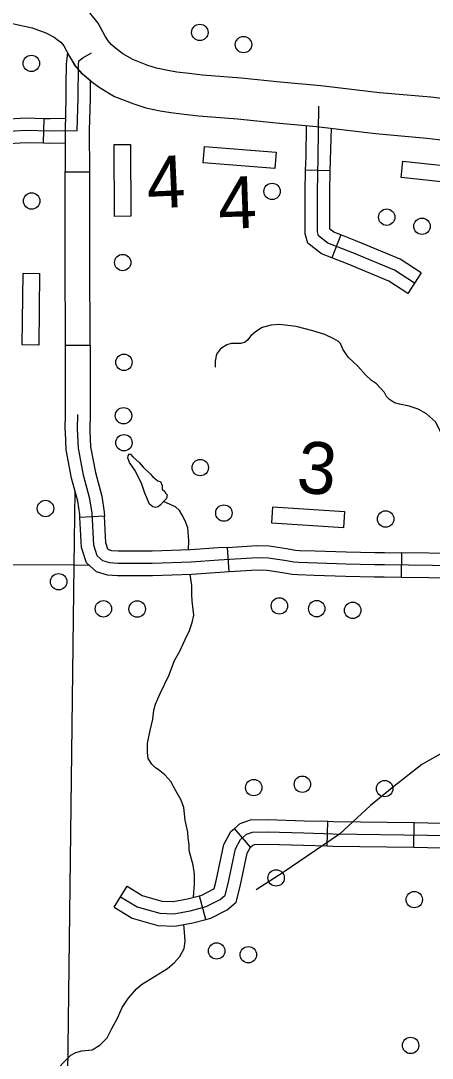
# Model space of a CAD drawing. Extents: x 22866 to 28196, y 1324810 to 1328105.
# Drawn here: x 25465.4 to 25525.6, y 1326340.7 to 1326492.6 of the extents above; entities that cross this region are included whole.
import ezdxf

# ---------------------------------------------------------------- set-up
doc = ezdxf.new("R2010")
doc.units = 0
for name, color, linetype in [('Level 10', 7, 'Continuous'), ('Level 31', 7, 'Continuous'), ('Level 32', 7, 'Continuous'), ('Level 34', 7, 'Continuous'), ('Level 35', 7, 'Continuous'), ('Level 5', 7, 'Continuous'), ('Level 56', 7, 'Continuous')]:
    doc.layers.add(name, color=color, linetype=linetype)

msp = doc.modelspace()

# ---------------------------------------------------------------- linework, layer by layer
at = {"layer": 'Level 10'}
for points in [[(25483.97, 1326486.04), (25481.75, 1326486.89), (25480.32, 1326487.75), (25479.48, 1326488.37), (25478.6, 1326489.1), (25478.14, 1326489.62), (25477.72, 1326490.32), (25476.7, 1326492.23), (25475.5, 1326493.72), (25474.58, 1326494.45), (25473.43, 1326495.3), (25471.42, 1326496.33), (25468.7, 1326497.28), (25466.13, 1326497.87), (25462.9, 1326498.6), (25457.93, 1326499.47), (25456.22, 1326499.8), (25452.62, 1326500.3), (25449.84, 1326500.5), (25447.36, 1326500.74), (25445.63, 1326500.86), (25443.19, 1326500.9), (25441.23, 1326500.79)], [(25442.62, 1326494.91), (25445.36, 1326494.86), (25446.86, 1326494.76), (25449.34, 1326494.52), (25452, 1326494.33), (25455.25, 1326493.88), (25456.85, 1326493.57), (25461.72, 1326492.71), (25464.8, 1326492.02), (25467.03, 1326491.51), (25469.04, 1326490.8), (25470.26, 1326490.18), (25470.92, 1326489.69), (25471.25, 1326489.43), (25471.68, 1326488.9), (25472.5, 1326487.35), (25473.27, 1326486.08), (25474.39, 1326484.79), (25475.79, 1326483.63), (25477, 1326482.75), (25479.11, 1326481.48), (25481.94, 1326480.39)], [(25559.75, 1326467.42), (25556.83, 1326471.16), (25554.9, 1326473.34), (25552.99, 1326475.26), (25551.5, 1326476.55), (25549.59, 1326477.63), (25547.36, 1326478.5), (25543.35, 1326479.14), (25539.62, 1326479.66), (25533.77, 1326480.34), (25525.38, 1326481.37), (25517.87, 1326482.04), (25509.28, 1326483.06), (25503.31, 1326483.58), (25497.62, 1326484.17), (25491.97, 1326484.6), (25489.99, 1326484.83), (25488.21, 1326485.06), (25486.87, 1326485.28), (25485.22, 1326485.62), (25483.97, 1326486.04)], [(25481.94, 1326480.39), (25483.65, 1326479.82), (25485.78, 1326479.37), (25487.35, 1326479.12), (25489.27, 1326478.87), (25491.39, 1326478.63), (25497.08, 1326478.19), (25502.74, 1326477.6), (25508.66, 1326477.09), (25517.25, 1326476.07), (25524.75, 1326475.4), (25533.06, 1326474.38), (25538.86, 1326473.71), (25542.46, 1326473.21), (25545.78, 1326472.67), (25547.01, 1326472.2), (25548.02, 1326471.62), (25548.89, 1326470.86), (25550.53, 1326469.23), (25552.22, 1326467.32), (25554.95, 1326463.82)]]:
    msp.add_lwpolyline(points, dxfattribs=at)
at = {"layer": 'Level 31'}
for p, q in [((25471.86, 1326470.43), (25475.46, 1326470.43)), ((25471.91, 1326445.08), (25475.51, 1326445.08)), ((25477.63, 1326420.05), (25474.03, 1326419.86)), ((25474.03, 1326419.86), (25474.03, 1326419.86)), ((25495.85, 1326411.87), (25495.64, 1326415.47)), ((25521.05, 1326414.67), (25521.01, 1326411.07))]:
    msp.add_line(p, q, dxfattribs=at)
for points in [[(25472.21, 1326487.9), (25472.01, 1326486.19), (25471.99, 1326483.12)], [(25475.59, 1326483.79), (25474.38, 1326484.8), (25473.26, 1326486.1), (25472.21, 1326487.9)], [(25475.59, 1326483.09), (25475.59, 1326483.79)], [(25471.99, 1326483.12), (25471.97, 1326481.32), (25471.85, 1326476.54), (25471.86, 1326470.43)], [(25475.46, 1326470.43), (25475.45, 1326476.5), (25475.57, 1326481.26), (25475.59, 1326483.08)], [(25441.82, 1326456.87), (25443.46, 1326458.92), (25446.53, 1326461.72), (25450.22, 1326464.53), (25451.96, 1326466.89), (25455.31, 1326471.03), (25456.44, 1326472.43), (25457.02, 1326473.66), (25457.36, 1326475.16), (25457.36, 1326476.11), (25457.63, 1326476.69), (25458.65, 1326477.34), (25459.14, 1326477.37), (25459.72, 1326477.17), (25460.68, 1326476.89), (25461.6, 1326476.52), (25462.9, 1326476.35), (25466.11, 1326476.55), (25469.66, 1326476.45), (25473.65, 1326476.52)], [(25471.88, 1326457.75), (25471.86, 1326470.43)], [(25475.48, 1326457.76), (25475.46, 1326470.43)], [(25471.91, 1326445.08), (25471.88, 1326457.75)], [(25475.51, 1326445.08), (25475.48, 1326457.76)], [(25471.9, 1326432.34), (25471.89, 1326432.76), (25471.92, 1326434.95), (25471.91, 1326445.08)], [(25475.51, 1326445.08), (25475.52, 1326434.93), (25475.49, 1326432.8), (25475.5, 1326432.48)], [(25474.03, 1326419.86), (25474.01, 1326420.27), (25473.71, 1326422.22), (25472.81, 1326425.62), (25472, 1326429.76), (25471.9, 1326432.34)], [(25475.5, 1326432.48), (25475.59, 1326430.18), (25476.32, 1326426.43), (25477.24, 1326422.96), (25477.6, 1326420.64), (25477.63, 1326420.05)], [(25483.09, 1326411.32), (25482.72, 1326411.32), (25479.51, 1326411.32), (25478.09, 1326411.4), (25476.47, 1326411.87), (25475.01, 1326413.2), (25474.27, 1326415.45), (25474.03, 1326419.86)], [(25483.09, 1326414.92), (25482.72, 1326414.92), (25479.62, 1326414.92), (25478.7, 1326414.97), (25478.27, 1326415.1), (25478.13, 1326415.22), (25477.84, 1326416.12), (25477.63, 1326420.05)], [(25495.64, 1326415.47), (25494.25, 1326415.39), (25490.22, 1326415.1), (25484.59, 1326414.92), (25483.09, 1326414.92)], [(25495.64, 1326415.47), (25499.92, 1326415.72), (25501.71, 1326415.68), (25504.24, 1326415.3), (25505.55, 1326415.08), (25506.14, 1326415.02), (25508.42, 1326414.95)], [(25508.42, 1326414.95), (25512.99, 1326414.81), (25517.16, 1326414.7), (25518.57, 1326414.7), (25521.05, 1326414.67)], [(25533.65, 1326414.73), (25529.09, 1326414.58), (25521.05, 1326414.67)], [(25508.31, 1326411.35), (25505.9, 1326411.43), (25505.08, 1326411.51), (25503.68, 1326411.74), (25501.4, 1326412.09), (25499.98, 1326412.12), (25495.85, 1326411.87)], [(25495.85, 1326411.87), (25494.48, 1326411.79), (25490.41, 1326411.5), (25484.65, 1326411.32), (25483.09, 1326411.32)], [(25521.01, 1326411.07), (25518.55, 1326411.1), (25517.12, 1326411.1), (25512.89, 1326411.21), (25508.31, 1326411.35)], [(25533.76, 1326411.13), (25529.13, 1326410.98), (25521.01, 1326411.07)]]:
    msp.add_lwpolyline(points, dxfattribs=at)
at = {"layer": 'Level 32'}
for p, q in [((25468.7, 1326474.68), (25468.8, 1326478.28)), ((25510.65, 1326470.6), (25507.05, 1326470.7)), ((25512.21, 1326461.21), (25510.9, 1326457.86)), ((25523.96, 1326455.66), (25522, 1326452.64)), ((25498.99, 1326371.59), (25496.63, 1326374.31)), ((25510.19, 1326371.76), (25510.29, 1326375.36)), ((25522.89, 1326371.57), (25522.94, 1326375.17)), ((25479.05, 1326362.79), (25480.93, 1326365.86)), ((25492.47, 1326361), (25491.54, 1326364.47))]:
    msp.add_line(p, q, dxfattribs=at)
for points in [[(25473.65, 1326476.52), (25473.77, 1326481.29), (25473.81, 1326486.07), (25473.88, 1326486.7), (25474.47, 1326487.13), (25475.71, 1326487.85)], [(25455.56, 1326475.55), (25455.56, 1326476.51), (25456.23, 1326477.93), (25458.07, 1326479.1), (25459.39, 1326479.19), (25460.27, 1326478.88), (25461.26, 1326478.6), (25462.06, 1326478.27), (25462.96, 1326478.15), (25466.08, 1326478.35), (25468.8, 1326478.28)], [(25520.05, 1326456.05), (25513.95, 1326458.59), (25510.28, 1326460.03), (25508.94, 1326461.06), (25508.77, 1326461.65), (25508.77, 1326462.49), (25508.77, 1326467.53), (25508.9, 1326472.61), (25508.97, 1326480.08)], [(25468.8, 1326478.28), (25469.67, 1326478.25), (25471.9, 1326478.29)], [(25507.05, 1326470.7), (25507.1, 1326472.64), (25507.15, 1326477.22)], [(25510.65, 1326470.6), (25510.82, 1326476.84)], [(25459.16, 1326475.45), (25459.17, 1326475.45), (25460.09, 1326475.19), (25461.13, 1326474.76), (25462.84, 1326474.54), (25466.14, 1326474.75), (25468.7, 1326474.68)], [(25468.7, 1326474.68), (25469.65, 1326474.65), (25471.85, 1326474.69)], [(25510.9, 1326457.86), (25509.38, 1326458.45), (25507.38, 1326459.99), (25506.97, 1326461.39), (25506.97, 1326462.49), (25506.97, 1326467.56), (25507.05, 1326470.7)], [(25512.21, 1326461.21), (25511.17, 1326461.62), (25510.57, 1326462.08), (25510.57, 1326462.49), (25510.57, 1326467.51), (25510.65, 1326470.6)], [(25523.96, 1326455.66), (25520.89, 1326457.65), (25514.62, 1326460.26), (25512.21, 1326461.21)], [(25522, 1326452.64), (25519.21, 1326454.45), (25513.27, 1326456.92), (25510.9, 1326457.86)], [(25522.98, 1326454.15), (25520.05, 1326456.05)], [(25479.56, 1326413.12), (25478.39, 1326413.19), (25477.37, 1326413.48), (25476.57, 1326414.21), (25476.06, 1326415.78), (25475.8, 1326420.46), (25475.48, 1326422.59), (25474.56, 1326426.03), (25473.8, 1326429.97), (25473.69, 1326432.78), (25473.72, 1326434.94)], [(25529.11, 1326412.78), (25518.56, 1326412.9), (25517.14, 1326412.9), (25512.94, 1326413.01), (25506.02, 1326413.23), (25505.31, 1326413.3), (25503.96, 1326413.52), (25501.55, 1326413.88), (25499.95, 1326413.92), (25494.37, 1326413.59), (25490.31, 1326413.3), (25484.62, 1326413.12), (25482.72, 1326413.12), (25479.56, 1326413.12)], [(25491.54, 1326364.47), (25491.88, 1326364.56), (25493.54, 1326365.4), (25493.67, 1326365.51), (25493.98, 1326366.66), (25495.08, 1326371.97), (25496.1, 1326373.86), (25496.63, 1326374.31)], [(25496.63, 1326374.31), (25497.47, 1326375.04), (25498.97, 1326375.57), (25501.5, 1326375.61), (25506.82, 1326375.45), (25510.29, 1326375.36)], [(25510.29, 1326375.36), (25511.11, 1326375.34), (25522.94, 1326375.17)], [(25522.94, 1326375.17), (25524.91, 1326375.14), (25533.99, 1326375.02), (25535.82, 1326374.76)], [(25495.73, 1326366.24), (25496.79, 1326371.34), (25497.53, 1326372.71), (25498.39, 1326373.46), (25499.29, 1326373.77), (25501.49, 1326373.81), (25506.77, 1326373.65), (25511.07, 1326373.54), (25524.88, 1326373.34), (25533.85, 1326373.22), (25536.05, 1326372.91), (25536.59, 1326372.52), (25536.95, 1326372.08), (25536.99, 1326371.38), (25536.91, 1326369.22), (25536.85, 1326363.05)], [(25492.47, 1326361), (25493.17, 1326361.18), (25495.58, 1326362.39), (25496.87, 1326363.53), (25497.48, 1326365.83), (25498.49, 1326370.71), (25498.96, 1326371.57), (25498.99, 1326371.59)], [(25498.99, 1326371.59), (25499.31, 1326371.87), (25499.61, 1326371.98), (25501.48, 1326372.01), (25506.72, 1326371.85), (25510.19, 1326371.76)], [(25510.19, 1326371.76), (25511.03, 1326371.74), (25522.89, 1326371.57)], [(25522.89, 1326371.57), (25524.86, 1326371.54), (25533.71, 1326371.42), (25535.31, 1326371.19)], [(25479.99, 1326364.32), (25482.42, 1326362.83), (25485.71, 1326361.89), (25487.79, 1326361.81), (25490.17, 1326362.25), (25492.52, 1326362.87), (25494.56, 1326363.89), (25495.27, 1326364.52), (25495.73, 1326366.24)], [(25480.93, 1326365.86), (25483.15, 1326364.5), (25486, 1326363.68), (25487.66, 1326363.62), (25489.78, 1326364), (25491.54, 1326364.47)], [(25479.05, 1326362.79), (25481.69, 1326361.17), (25485.42, 1326360.1), (25487.91, 1326360.01), (25490.57, 1326360.49), (25492.47, 1326361)]]:
    msp.add_lwpolyline(points, dxfattribs=at)
at = {"layer": 'Level 34'}
msp.add_lwpolyline([(25533.04, 1326388.54), (25528.54, 1326386.21), (25524.03, 1326383.66), (25519.71, 1326380.28), (25516.54, 1326377.69), (25511.99, 1326373.49), (25503.77, 1326367.86), (25499.81, 1326365.31)], dxfattribs=at)
at = {"layer": 'Level 35'}
for points in [[(25512.47, 1326444.48), (25512.17, 1326445.31), (25511.85, 1326445.63), (25511.17, 1326446.02), (25509.84, 1326446.62), (25508.09, 1326447.17), (25505.66, 1326447.8), (25503.2, 1326448.11), (25502, 1326448.01), (25500.69, 1326447.64), (25499.73, 1326447.04), (25498.99, 1326446.41), (25498.58, 1326445.84), (25498.18, 1326445.52), (25497.56, 1326445.31), (25496.9, 1326445.31), (25496.14, 1326445.31), (25495.52, 1326445.13), (25494.6, 1326444.55), (25494, 1326443.74), (25493.79, 1326442.75), (25493.79, 1326441.86)], [(25523.52, 1326435.68), (25522.2, 1326436.13), (25520.79, 1326436.42), (25520.05, 1326436.63), (25519.3, 1326437.1), (25518.88, 1326437.57), (25518.59, 1326438.12), (25517.41, 1326439.4), (25516.68, 1326439.92), (25515.82, 1326440.71), (25514.69, 1326441.99), (25513.31, 1326443.25), (25512.76, 1326444.06), (25512.47, 1326444.48)], [(25538.62, 1326421.96), (25537.06, 1326422.65), (25534.89, 1326423.88), (25533.74, 1326425.03), (25532.96, 1326425.5), (25532.41, 1326425.6), (25531.81, 1326425.84), (25531.26, 1326426.39), (25530.74, 1326426.97), (25530.29, 1326427.46), (25529.85, 1326427.91), (25529.14, 1326428.51), (25528.31, 1326429.37), (25527.47, 1326430.44), (25527.13, 1326431.33), (25526.87, 1326432.2), (25526.55, 1326432.9), (25526.03, 1326433.87), (25524.72, 1326435), (25523.52, 1326435.68)], [(25482.99, 1326424.96), (25482.05, 1326426.76), (25481.3, 1326427.87), (25481.05, 1326428.58), (25481.08, 1326428.87), (25481.26, 1326429.15), (25481.44, 1326429.12), (25481.76, 1326428.72), (25482.72, 1326427.87), (25483.26, 1326427.19), (25484.36, 1326426.16), (25484.68, 1326425.77)], [(25484.68, 1326425.77), (25485.43, 1326425.23), (25485.82, 1326425.09), (25486.07, 1326424.52), (25486.07, 1326423.99), (25486.43, 1326423.66), (25486.57, 1326423.42), (25486.78, 1326423.17), (25486.71, 1326422.6), (25486.28, 1326422.17)], [(25486.28, 1326422.2), (25485.82, 1326421.67), (25485.46, 1326421.38), (25485.07, 1326421.31), (25484.72, 1326421.38), (25484.22, 1326421.78), (25483.54, 1326423.42), (25483.08, 1326424.7), (25482.99, 1326424.96)], [(25488.6, 1326420.86), (25487.99, 1326421.42), (25487.24, 1326421.74), (25486.28, 1326422.2)], [(25489.93, 1326415.09), (25489.95, 1326416.48), (25489.84, 1326418.33), (25489.42, 1326419.33), (25488.95, 1326420.29), (25488.6, 1326420.86)], [(25490.7, 1326405.56), (25490.59, 1326406.39), (25490.45, 1326407.64), (25490.38, 1326408.57), (25490.38, 1326409.88), (25490.16, 1326411.49)], [(25483.93, 1326386.73), (25484.11, 1326387.71), (25484.29, 1326388.67), (25484.72, 1326390.31), (25484.86, 1326391.63), (25485.11, 1326392.52), (25485.75, 1326394.05), (25487.07, 1326396.79), (25487.85, 1326398.9), (25488.63, 1326400.29), (25489.42, 1326401.96), (25490.06, 1326403.28), (25490.45, 1326404.49), (25490.7, 1326405.56)], [(25490.23, 1326370.37), (25489.99, 1326371.06), (25489.99, 1326371.91), (25489.88, 1326372.87), (25489.84, 1326373.76), (25489.45, 1326375.51), (25489.24, 1326377.36), (25488.85, 1326378.47), (25488.06, 1326379.82), (25487.32, 1326381.18), (25486.46, 1326382.17), (25485.5, 1326382.92), (25485.11, 1326383.21), (25484.57, 1326383.74), (25484, 1326384.53), (25483.93, 1326385.45), (25483.93, 1326386.73)], [(25490.64, 1326364.23), (25490.77, 1326366.2), (25490.8, 1326367.62), (25490.59, 1326368.94), (25490.23, 1326370.37)], [(25474.29, 1326341.74), (25475.82, 1326341.88), (25476.96, 1326342.56), (25478.02, 1326343.66), (25478.7, 1326345.02), (25479.52, 1326346.55), (25480.19, 1326348.12), (25481.08, 1326349.4), (25482.33, 1326350.82), (25483.04, 1326351.48), (25484.93, 1326352.62), (25486.85, 1326353.83), (25487.88, 1326354.69), (25488.63, 1326355.54), (25489.27, 1326356.75), (25489.45, 1326357.82), (25489.31, 1326359.14), (25489.22, 1326360.24)], [(25465.28, 1326324.06), (25465.88, 1326324.74), (25466.28, 1326325.67), (25466.35, 1326326.63), (25466.42, 1326327.55), (25466.95, 1326328.91), (25467.31, 1326329.37), (25467.7, 1326329.66), (25468.34, 1326329.87), (25468.95, 1326329.98), (25469.41, 1326330.55), (25469.55, 1326331.15), (25469.66, 1326331.83), (25469.62, 1326332.9), (25469.51, 1326334.18), (25469.44, 1326335.64), (25469.73, 1326337.43), (25470.37, 1326338.67), (25471.69, 1326340.1), (25472.72, 1326341.13), (25473.43, 1326341.49), (25474.29, 1326341.74)]]:
    msp.add_lwpolyline(points, dxfattribs=at)
at = {"layer": 'Level 5'}
for points in [[(25473.2, 1326412.84), (25473.32, 1326423.68)], [(25473.2, 1326412.84), (25347.46, 1326413.55)], [(25471.64, 1326287.38), (25473.2, 1326412.84)], [(25475.43, 1326412.81), (25473.2, 1326412.84)]]:
    msp.add_lwpolyline(points, dxfattribs=at)
at = {"layer": 'Level 56'}
for points in [[(25479.02, 1326474.44), (25481.42, 1326474.45), (25481.5, 1326463.95), (25479.1, 1326463.93)], [(25492.08, 1326471.78), (25492.27, 1326474.17), (25502.74, 1326473.33), (25502.55, 1326470.93)], [(25521.01, 1326469.64), (25521.27, 1326472.03), (25531.71, 1326470.88), (25531.45, 1326468.5)], [(25465.74, 1326455.6), (25468.14, 1326455.57), (25468, 1326445.07), (25465.6, 1326445.1)], [(25502.1, 1326418.99), (25502.25, 1326421.38), (25512.73, 1326420.72), (25512.58, 1326418.33)]]:
    msp.add_lwpolyline(points, close=True, dxfattribs=at)
for centre in [(25491.57, 1326490.86), (25497.96, 1326489.08), (25466.93, 1326486.33), (25502.14, 1326467.58), (25466.97, 1326466.18), (25518.91, 1326463.81), (25524.07, 1326462.48), (25480.29, 1326457.17), (25480.47, 1326442.56), (25480.41, 1326434.74), (25480.47, 1326430.78), (25491.63, 1326427.15), (25469, 1326421.16), (25495.09, 1326420.48), (25518.75, 1326419.62), (25470.92, 1326410.43), (25477.47, 1326406.47), (25482.41, 1326406.44), (25503.21, 1326406.9), (25508.67, 1326406.49), (25513.93, 1326406.25), (25506.57, 1326380.79), (25499.46, 1326380.29), (25518.61, 1326380.15), (25502.73, 1326367.07), (25522.94, 1326363.89), (25494.03, 1326356.38), (25498.67, 1326355.82), (25522.4, 1326342.54)]:
    msp.add_circle(centre, 1.2, dxfattribs=at)

# ---------------------------------------------------------------- texts
for s, rotation, p in [('4', 2.6049, (25483.95, 1326465.06)), ('4', 2.0115, (25494.36, 1326462.07)), ('3', 354.4675, (25505.56, 1326423.58))]:
    msp.add_text(s, height=7.6, rotation=rotation, dxfattribs=at).set_placement(p)

doc.saveas('drawing.dxf')
